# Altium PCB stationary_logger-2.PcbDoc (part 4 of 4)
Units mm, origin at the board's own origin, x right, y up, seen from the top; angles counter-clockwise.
Board outline 105 x 45 mm, 4 copper layers (Top Layer, Layer 2, Layer 3, Bottom Layer), stack 1.492 mm thick; 317 components, 187 nets, 816 pads, 302 vias.
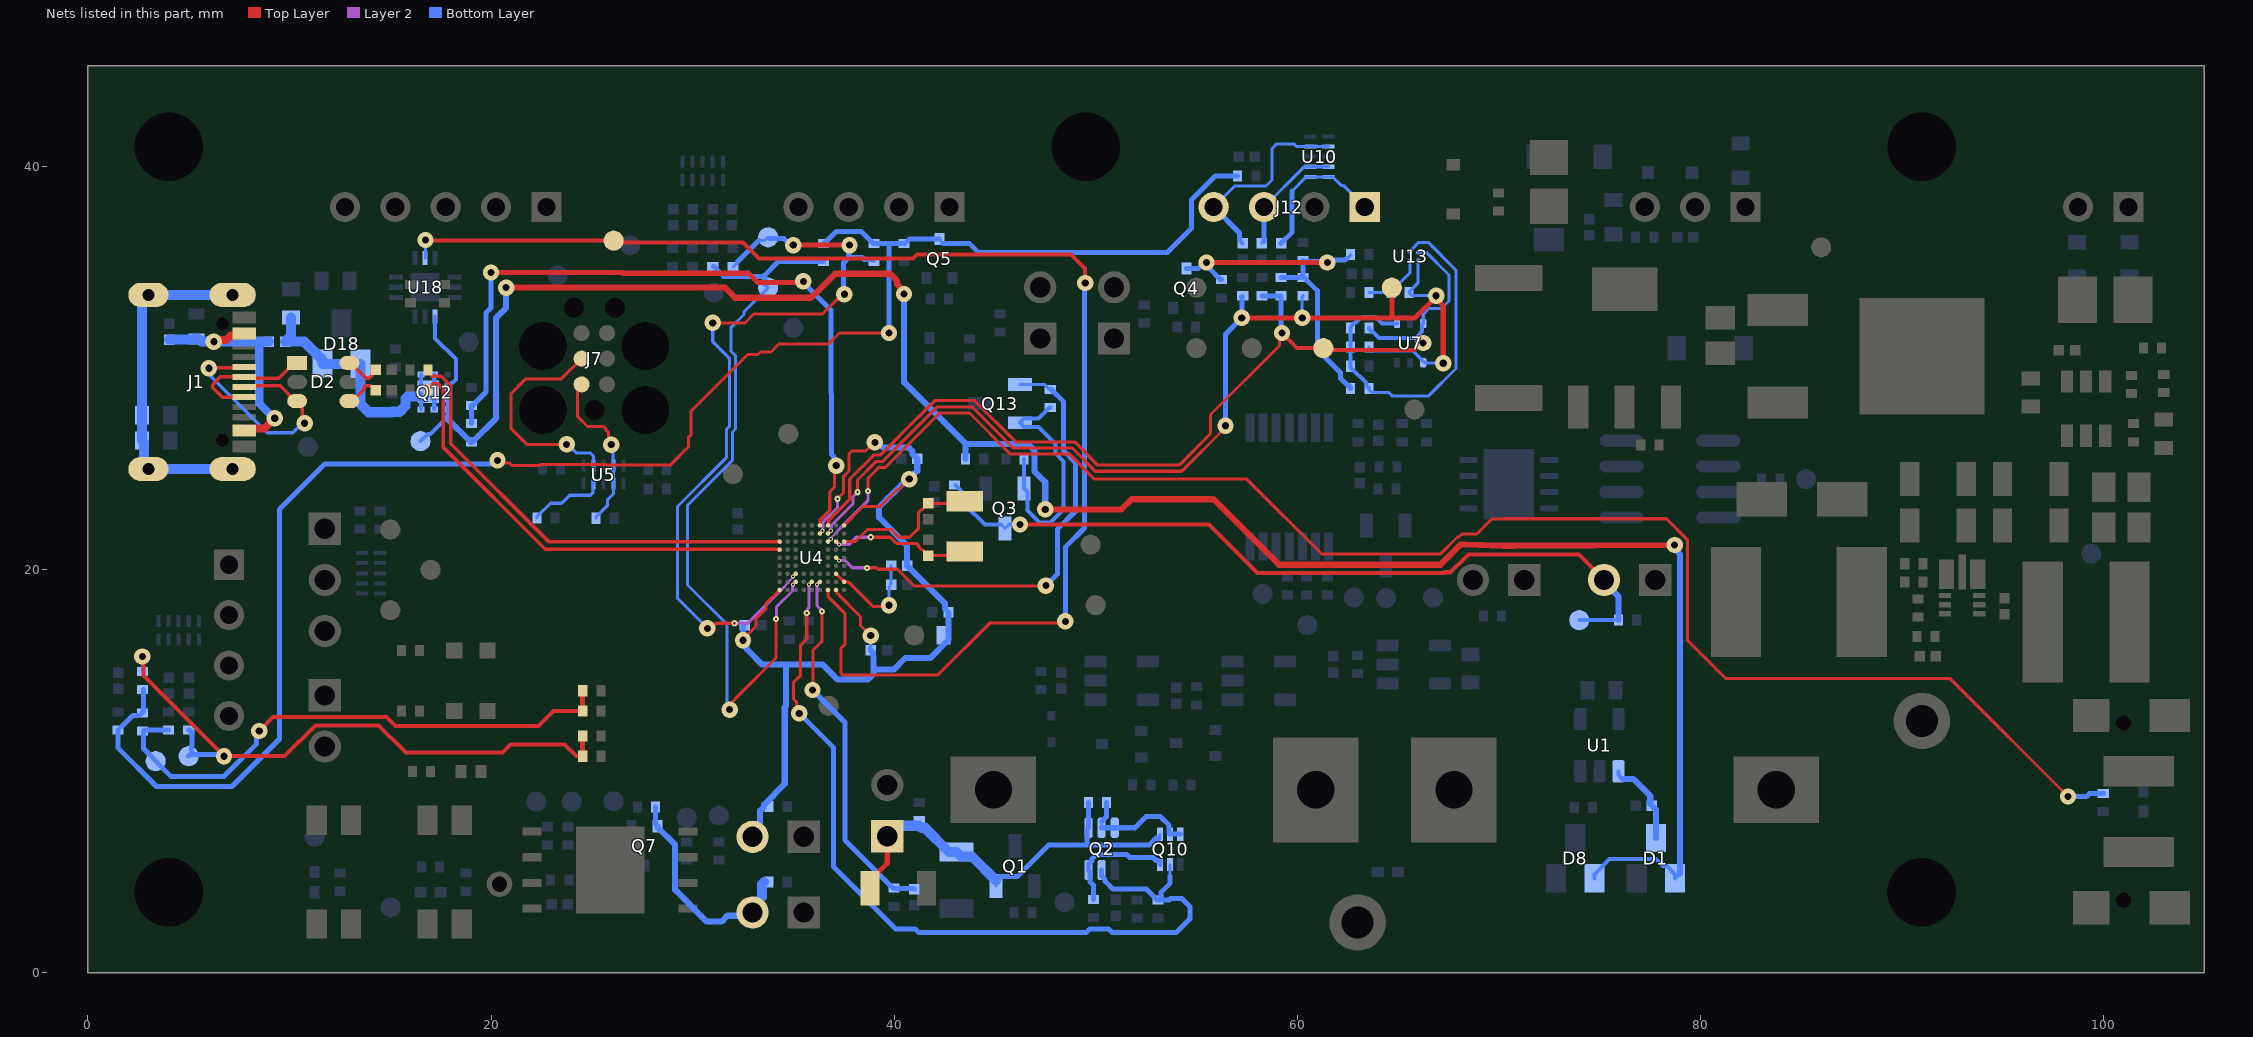
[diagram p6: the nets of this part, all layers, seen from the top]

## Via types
v1: diameter 0.813, hole 0.356, Top Layer to Bottom Layer, tented both sides, 238 vias
v2: diameter 0.305, hole 0.102, Top Layer to Layer 2, tented both sides, 29 vias
v3: diameter 0.203, hole 0.102, Top Layer to Layer 2, tented both sides, 27 vias
v4: diameter 0.305, hole 0.13, Top Layer to Bottom Layer, tented both sides, 8 vias

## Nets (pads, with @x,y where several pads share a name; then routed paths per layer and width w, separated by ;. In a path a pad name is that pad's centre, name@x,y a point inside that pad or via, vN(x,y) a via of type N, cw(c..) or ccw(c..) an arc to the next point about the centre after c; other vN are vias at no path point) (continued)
SENSE.VBAT_MEAS_EN: Q2.2 Q10.2 R17.1 U4.H5 | length 42.4
  Top Layer w0.152: v1(35.292,12.876) 35.166,13.002 35.166,13.433 35.012,13.587 35.012,14.424 35.361,14.773 35.361,16.262 35.666,16.567 v2(35.666,17.851)
  Layer 2 w0.152: 35.695,18.038 35.768,18.111 35.768,19.152 35.774,19.158 35.774,19.254 v3(35.783,19.263)
  Bottom Layer w0.152: 53.7,4.8 Q10.2@53.7,5.38
  Bottom Layer w0.25: v1(35.292,12.876) 37,11.167 37,5.25 40.066,2.184 41.033,2.184 41.217,2 49.533,2 49.717,2.184 50.641,2.184 50.825,2 54,2 54.684,2.684 54.684,3.283 54.283,3.684 53.717,3.684 53.657,3.624 R17.1@53.15,3.624 ; Q2.2@50.3,5.1 50.3,4.8 50.473,4.627 50.473,4.544 50.854,4.162 52.512,4.162 53.05,3.624 R17.1@53.1,3.624 R17.1@53.15,3.624 ; 53.7,4.8 53.7,4.45 53.25,4 53.25,3.724 R17.1@53.15,3.624
SWCLK: J7.4 R39.1 U5.4 U5.7 | length 15.7
  Top Layer w0.152: v1(23.75,26.222) 21.778,26.222 21,27 21,28.75 21.722,29.472 23.491,29.472 J7.4@24.492,30.473
  Bottom Layer w0.152: R39.1@22.275,22.575 22.275,22.625 22.952,23.302 23.502,23.302 23.9,23.7 24.928,23.7 25.053,23.825 25.053,24.248 U5.4@25.077,24.272 U5.7@25.077,25.172 25.077,25.646 24.935,25.787 24.604,25.787 24.589,25.802 24.228,25.802 23.808,26.222 v1(23.75,26.222)
SWDIO: J7.2 R37.1 U5.2 U5.9 | length 8.3
  Top Layer w0.152: J7.2@24.492,29.203 24.492,29.028 24.3,28.836 24.3,27.6 24.79,27.11 25.589,27.11 25.695,27.004 25.695,26.945 25.835,26.805 25.835,26.338 v1(25.962,26.212)
  Bottom Layer w0.152: R37.1@25.202,22.56 25.202,22.61 25.788,23.195 25.788,23.488 26.077,23.777 U5.2@26.077,24.272 U5.9@26.077,25.172 26.053,25.196 26.053,26.12 v1(25.962,26.212)
TEMP_ADD0: R52.1 R53.1 R55.1 R58.1 U7.4 U13.B2 | length 19.1
  Bottom Layer w0.152: R53.1@63.557,29 63.557,28.95 63.705,28.801 64.551,28.801 64.737,28.615 66.51,28.615 67.883,29.988 67.883,34.867 66.5,36.25 66.042,36.25 65.678,35.886 65.678,35.834 65.607,35.763 U13.B2@65.607,35.75
  Bottom Layer w0.2: R53.1@63.557,29 63.432,29.125 63.432,29.275 62.657,30.05 R52.1@62.657,30.1 R58.1@62.657,31.05 62.657,32.051 62.869,32.263 62.93,32.263 63.195,32.528 63.915,32.528 64.218,32.225 U7.4@64.957,32.225
TEMP_ADD1: R4.1 R83.2 U13.A2 | length 3.1
  Bottom Layer w0.152: R4.1@63.557,33.75 R83.2@64.657,33.75 64.657,33.8 65.607,34.75 U13.A2@65.607,35.35
TEMPA_I2C.SCL: R60.2 R91.2 R94.1 R97.2 TP37.1 | length 31.2
  Top Layer w0.2: v1@2.75,16 2.75,14.75 v1(6.75,10.75) 9.75,10.75 11.282,12.282 14.422,12.282 15.772,10.932 20.567,10.932 20.977,11.343 23.657,11.343 24.25,10.75 R97.2@24.55,10.75
  Top Layer w0.25: R97.2@24.55,10.75 R60.2@24.55,11.75
  Bottom Layer w0.152: R91.2@2.7,14.97 v1(2.7,15.699)
  Bottom Layer w0.25: TP37.1@5,10.75 TP37.1@5.084,10.834 ; R94.1@5,12.05 5.05,12.05 5.15,11.95 5.15,11.82 5.166,11.804 5.166,11.271 5.144,11.249 5.144,10.894 TP37.1@5.084,10.834 ; v1(6.75,10.75) 6.666,10.834 TP37.1@5.084,10.834
TEMPA_I2C.SDA: R51.2 R73.2 R92.2 R93.1 TP24.1 | length 27.6
  Top Layer w0.2: v1(8.5,12) 9.193,12.693 14.807,12.693 15.25,12.25 22.361,12.25 23.111,13 R51.2@24.55,13
  Top Layer w0.25: R51.2@24.55,13 R73.2@24.55,14.07
  Bottom Layer w0.152: R92.2@2.702,11.978 R92.2@2.773,12.05 ; v1@8.374,11.874 v1(8.5,12)
  Bottom Layer w0.25: R92.2@2.75,11.93 2.75,11.131 3.358,10.523 TP24.1@3.358,10.502 4.11,9.75 6.75,9.75 8.374,11.374 v1@8.374,11.874 ; R92.2@2.773,12.05 R93.1@4,12.05
TEMPF_I2C.SCL: R23.2 R89.1 TP17.1 U4.H3 | length 37.9
  Top Layer w0.152: v1(31.836,13.062) 31.963,13.188 31.963,13.444 32.268,13.75 34.142,15.624 v2(34.142,17.552)
  Layer 2 w0.152: v2(34.142,17.552) 34.167,17.577 34.167,18.162 34.955,18.949 34.955,19.152 34.974,19.171 34.974,19.254 v3(34.983,19.263)
  Bottom Layer w0.152: R89.1@31,35.05 R89.1@31.05,35.05 ; v1(31.836,13.062) 31.71,13.188 31.71,17.29 29.75,19.25 29.75,23.207 31.98,25.437 31.98,26.836 32.128,26.984 32.128,30.626 31.9,30.855 31.9,32.013 32.553,32.667 32.553,32.803 TP17.1@33.75,34 TP17.1@33.588,34.162 ; 33.551,34.596 33.588,34.559
  Bottom Layer w0.25: R89.1@31.05,35.05 31.541,34.559 31.599,34.559 31.61,34.548 32.39,34.548 32.401,34.559 33.588,34.559 TP17.1@33.588,34.162 ; 33.551,34.596 34.254,35.3 R23.2@36.5,35.3
TEMPF_I2C.SDA: R24.2 R88.1 TP15.1 U4.G3 | length 40.3
  Top Layer w0.152: v1(30.738,17.094) 30.917,17.094 31.171,17.349 v2(32.085,17.349) ; v1(31,32.25) 32.604,32.25 33.044,32.69 36.44,32.69 37.426,33.676 v1(37.535,33.676) ; v3(34.983,19.663) U4.G3@35.12,19.8
  Top Layer w0.25: v1(35,36.113) v1(37.785,36.113)
  Layer 2 w0.102: 34.588,19.19 34.588,19.2 34.818,19.43 34.818,19.471 34.983,19.636 v3(34.983,19.663)
  Layer 2 w0.152: v2(32.085,17.349) 32.746,17.349 34.588,19.19
  Bottom Layer w0.152: v1(30.738,17.094) 29.25,18.583 29.25,23.138 31.675,25.563 31.675,26.963 31.823,27.111 31.823,30.5 31,31.323 v1(31,32.25) ; R88.1@32,35.05 32.05,35.05 32.199,35.199 R88.1@32.199,35.249 ; TP15.1@33.288,36.338 33.588,36.338 TP15.1@33.75,36.5 TP15.1@33.818,36.432 ; R24.2@38.894,35.406 R24.2@39,35.3
  Bottom Layer w0.25: R88.1@32.199,35.249 TP15.1@33.288,36.338 ; TP15.1@33.818,36.432 34.529,36.432 34.848,36.113 v1(35,36.113) ; v1(37.535,33.676) 37.5,33.712 37.5,35.25 37.75,35.5 ; v1(37.785,36.113) 37.75,36.079 37.75,35.5 ; R24.2@38.894,35.406 38.496,35.406 38.403,35.5 37.75,35.5
TEMPV_I2C.SCL: R19.2 R58.2 R62.1 R83.1 TP9.1 U4.B7 U7.1 U13.A3 | length 55.7
  Top Layer w0.152: U4.B7@36.72,21.8 v3(36.857,21.937) ; v2(38.181,23.851) 38.181,24.452 39.111,25.382 39.439,25.382 40.609,26.552 40.609,26.558 42.136,28.085 43.864,28.085 45.906,26.044 47.747,26.044 47.748,26.043 48.835,26.043 49.987,24.89 54.27,24.89 56.443,27.064 v1(56.443,27.147) ; v1(66.898,33.602) 66.923,33.577 v1@66.949,33.551
  Top Layer w0.25: v1(57.25,32.5) v1(60.25,32.5) 64.7,32.5 ; TP9.1@64.7,34 64.7,32.5 ; v1@66.923,33.577 65.847,32.5 64.7,32.5 ; v1@66.949,33.551 66.949,33.399 67.25,33.098 v1(67.25,30.25)
  Layer 2 w0.152: v3(36.857,21.937) 36.866,21.946 36.866,22.08 36.885,22.099 36.885,22.2 37.952,23.267 37.952,23.61 38.181,23.839 v2(38.181,23.851)
  Bottom Layer w0.152: R62.1@57.25,33.547 R62.1@57.3,33.597 ; v1(60.25,32.5) 60.25,33.548 R19.2@60.3,33.597 ; R58.2@63.557,31.05 63.557,31 63.705,30.851 65.755,30.851 66.257,30.35 66.257,30.324 66.318,30.263 67.237,30.263 v1(67.25,30.25) ; U13.A3@66.007,35.35 66.007,34.25 65.557,33.8 R83.1@65.557,33.75 65.704,33.602 v1(66.898,33.602)
  Bottom Layer w0.25: v1(56.443,27.147) 56.443,31.693 v1(57.25,32.5) 57.275,32.525 57.275,33.522 R62.1@57.25,33.547
TEMPV_I2C.SDA: R20.2 R55.2 R61.1 TP8.1 U4.A7 U7.6 U13.B3 | length 49.7
  Top Layer w0.152: U4.A7@36.72,22.2 36.72,22.22 36.758,22.258 36.758,22.454 37.8,23.496 37.8,24.502 38.984,25.687 39.313,25.687 40.304,26.679 40.304,26.684 42.01,28.39 43.99,28.39 46.032,26.348 47.873,26.348 47.874,26.347 48.961,26.347 50.114,25.195 54.143,25.195 55.705,26.757 55.705,27.705 59.124,31.124 59.124,31.624 v1(59.25,31.75)
  Top Layer w0.2: v1(59.25,31.75) 60,31 TP8.1@61.3,31 61.4,30.9 65.829,30.9 66.181,31.252 v1(66.252,31.252)
  Bottom Layer w0.152: U13.B3@66.007,35.75 66.411,35.75 67.533,34.628 67.533,33.339 67.161,32.967 66.545,32.967 66.257,32.679 U7.6@66.257,32.225
  Bottom Layer w0.2: R55.2@63.557,32.001 63.557,31.951 63.682,31.826 63.732,31.826 64.057,31.5 65.883,31.5 ; 65.944,31.561 66.207,31.824 66.207,32.175 U7.6@66.257,32.225
  Bottom Layer w0.25: R61.1@58.25,33.597 R20.2@59.2,33.597 59.2,31.8 v1(59.25,31.75)
USB.D_N: R8.1 U4.D1 | length 22.7
  Top Layer w0.178: R8.1@16.88,28.92 17.016,29.056 17.016,29.125 17.121,29.229 17.372,29.229 17.619,28.982 17.619,26.092 22.692,21.019 32.919,21.019 32.928,21.009 33.159,21.009 34.277,21.009 34.287,21 U4.D1@34.32,21
USB.D_P: R9.1 U4.C1 | length 22.7
  Top Layer w0.178: R9.1@16.88,29.92 17.016,29.784 17.016,29.715 17.121,29.61 17.53,29.61 18,29.14 18,26.25 22.85,21.4 33.076,21.4 33.086,21.39 33.159,21.39 34.311,21.39 U4.C1@34.32,21.4
USB.DETECT: R5.1 R7.2 U4.A6 | length 36.8
  Top Layer w0.152: v1@35.438,34.25 v1(35.5,34.312) ; U4.A6@36.32,22.2 36.334,22.214 36.334,22.487 36.809,22.962 36.809,23.862 37.038,24.091 37.038,25.08 v1(37.126,25.169)
  Top Layer w0.25: v1(20,34.75) 26.505,34.75 26.54,34.715 32.785,34.715 33.25,34.25 v1@35.438,34.25
  Bottom Layer w0.152: 19.724,32.724 19.75,32.75 ; v1@35.5,34.25 v1(35.5,34.312) ; 36.865,28.737 36.885,28.717 ; v1@37,25.295 v1(37.126,25.169)
  Bottom Layer w0.25: R5.1@19.032,27.25 R7.2@19.032,28.15 19.082,28.15 19.75,28.818 19.75,32.75 20,33 v1(20,34.75) ; v1@35.5,34.25 36.865,32.885 36.865,28.737 ; 36.885,28.717 36.885,25.745 36.991,25.639 36.991,25.605 37.019,25.578 37.019,25.314 v1@37,25.295
USB.DISCONN: Q13.1 R22.2 U4.E8 | length 23.4
  Top Layer w0.152: v2@38.673,20.102 39.122,20.102 39.198,20.026 40.165,20.026 40.986,19.205 47.513,19.205 v1@47.524,19.216
  Layer 2 w0.152: v3@37.266,20.463 37.272,20.457 37.571,20.457 37.927,20.102 v2@38.653,20.102 ; v2@38.673,20.102 38.841,20.102
  Bottom Layer w0.152: Q13.1@46.241,29.2 47.45,29.2 47.7,28.95 R22.2@47.75,28.95
  Bottom Layer w0.25: v1(47.534,19.216) 48.098,19.78 48.098,22.013 49,22.915 49,25.318 48.414,25.904 48.414,28.336 47.8,28.95 R22.2@47.75,28.95
  other v2: 38.663,20.092
  other v3: 37.257,20.463
USB.nFLT: TP14.1 U4.J7 U18.11 | length 69.2
  Top Layer w0.152: U4.J7@36.72,19 36.726,18.994 36.726,18.659 37.574,17.811 37.574,17.428 37.571,17.425 37.571,16.316 37.365,16.11 37.365,14.859 37.454,14.77 42.154,14.77 44.739,17.355 48.415,17.355 v1(48.5,17.44)
  Top Layer w0.2: v1(16.75,36.367) 16.768,36.349 25.986,36.349 26.084,36.251 32.499,36.251 33.293,35.457 40.933,35.457 41.132,35.656 48.772,35.656 49.484,34.944 v1(49.484,34.234)
  Bottom Layer w0.152: U18.11@16.73,35.47 16.74,35.48 16.74,36.358 v1(16.75,36.367)
  Bottom Layer w0.25: v1(48.5,17.44) 48.5,21.123 49.449,22.071 49.449,33.914 49.484,33.949 v1(49.484,34.234)
USB_CONN_D_N: D2.3 J1.A7 J1.B7 | length 12.4
  Top Layer w0.178: v1(6,30) 6.035,30.035 7.72,30.035 J1.B7@7.755,30.07 ; J1.A7@7.755,29.07 7.814,29.129 8.92,29.129 9.54,29.13 10.299,28.37 10.391,28.37 10.628,28.133 10.628,27.397 v1(10.749,27.276)
  Bottom Layer w0.178: v1(6,30) 6.122,29.879 6.122,29.578 8.9,26.8 10.169,26.8 10.645,27.276 v1(10.749,27.276)
USB_CONN_D_P: D2.1 J1.A6 J1.B6 | length 6.6
  Top Layer w0.178: J1.B6@7.755,28.57 6.656,28.57 6.187,29.039 6.187,29.187 6.57,29.57 J1.A6@7.755,29.57 7.814,29.51 8.762,29.51 9.471,29.511 10.23,30.27 D2.1@10.38,30.27
USB_CONN_VBUS: C7.2 D19.K FB1.1 J1.A4_B9 J1.B4_A9 | length 12.6
  Top Layer w0.4: v1(6.25,31.32) 6.329,31.399 6.861,31.399 7.082,31.62 7.655,31.62 J1.A4_B9@7.755,31.72 ; J1.B4_A9@7.755,26.92 7.855,27.02 8.77,27.02 v1(9.268,27.518)
  Bottom Layer w0.4: 8.5,31.32 8.5,28.25 9.232,27.518 v1(9.268,27.518)
  Bottom Layer w0.5: C7.2@4.03,31.42 5.225,31.42 5.255,31.45 D19.K@5.38,31.45 5.505,31.45 5.635,31.32 v1(6.25,31.32) 8.5,31.32 FB1.1@8.98,31.32
USB_ESD_D_N: D2.4 FB9.1 | length 1.8
  Top Layer w0.178: D2.4@12.97,28.37 13.12,28.37 13.707,28.956 13.707,29.082 13.754,29.129 14.005,29.129 14.043,29.091 14.109,29.091 FB9.1@14.28,28.92
USB_ESD_D_P: D2.6 FB10.1 | length 1.8
  Top Layer w0.178: D2.6@12.97,30.27 13.035,30.27 13.795,29.51 13.958,29.51 14.109,29.662 14.109,29.749 FB10.1@14.28,29.92
USB_SHIELD: C11.1 J1.S1 J1.S2 J1.S3 J1.S4 R6.1 | length 17.3
  Bottom Layer w0.5: J1.S4@7.18,25 J1.S3@3,25 2.78,25.22 2.78,26.32 C11.1@2.68,26.42 R6.1@2.68,27.67 2.68,33.409 2.911,33.64 J1.S2@3,33.64 J1.S1@7.18,33.64
USER_BUTTON: R33.1 U4.C7 | length 78.9
  Top Layer w0.152: U4.C7@36.72,21.4 v3(36.857,21.537) ; v2(38.714,23.902) 38.714,24.554 39.237,25.077 39.565,25.077 40.914,26.426 40.914,26.432 42.262,27.781 43.738,27.781 45.779,25.739 47.621,25.739 47.622,25.738 48.709,25.738 49.947,24.5 57.5,24.5 61.207,20.793 67.118,20.793 67.954,21.629 68.025,21.629 68.176,21.78 68.912,21.78 69.656,22.524 70.229,22.524 70.238,22.533 78.325,22.533 79.365,21.493 79.365,16.515 81.28,14.6 92.4,14.6 v1(98.25,8.75)
  Layer 2 w0.102: v3(36.857,21.537) 36.857,21.564 37.022,21.729 37.022,21.761 37.195,21.934 37.204,21.934
  Layer 2 w0.152: 37.204,21.934 38.714,23.444 v2(38.714,23.902)
  Bottom Layer w0.25: v1(98.25,8.75) 99.178,8.75 99.328,8.9 R33.1@100,8.9
VAX_SCL: FB5.2 J12.4 U10.4 U10.7 | length 10.4
  Bottom Layer w0.152: J12.4@55.857,38 56.903,39.046 58.457,39.046 58.75,39.339 58.75,40.893 58.992,41.135 59.824,41.135 59.959,41 U10.4@60.657,41 U10.7@61.557,41
  Bottom Layer w0.2: FB5.2@57.14,36.357 FB5.2@57.3,36.197
  Bottom Layer w0.25: J12.4@55.857,38 57.14,36.717 FB5.2@57.14,36.357
VAX_SDA: FB4.2 J12.3 U10.2 U10.9 | length 5.9
  Bottom Layer w0.152: FB4.2@58.25,36.197 FB4.2@58.357,36.304 ; J12.3@58.357,38 60.357,40 U10.2@60.657,40 U10.9@61.557,40
  Bottom Layer w0.25: FB4.2@58.357,36.304 J12.3@58.357,38
VAX_VDD: FB3.2 J12.1 U10.1 U10.10 | length 7.3
  Bottom Layer w0.152: 59.75,38.793 60.457,39.5 U10.1@60.657,39.5 U10.10@61.557,39.5 61.757,39.5 62.182,39.075 62.282,39.075 J12.1@63.357,38
  Bottom Layer w0.25: FB3.2@59.2,36.197 59.75,36.747 59.75,38.793
VB1: Q2.5 Q2.6 Q10.5 Q10.6 R15.2 | length 6.1
  Bottom Layer w0.152: Q2.5@50.3,7.2 Q2.5@50.3,7.513
  Bottom Layer w0.25: Q2.5@50.3,7.2 Q2.6@50.95,7.2 51.95,7.2 52.5,7.75 53.222,7.75 53.652,7.32 53.652,6.927 Q10.5@53.7,6.88 Q10.6@54.2,6.88 ; Q2.5@50.3,7.513 50.55,7.763 R15.2@50.55,8.45
VB2: Q2.3 Q10.3 R16.1 | length 5.9
  Bottom Layer w0.25: R16.1@49.9,3.65 49.9,4.35 49.725,4.525 49.725,5.025 Q2.3@49.65,5.1 49.65,5.4 49.823,5.573 49.823,5.656 50.049,5.882 51.531,5.882 51.683,5.731 52.849,5.731 53,5.58 53.15,5.58 53.2,5.53 Q10.3@53.2,5.38
VBAT: C12.2 C23.2 J2.1 Q1.2 Q2.4 Q10.4 R12.1 R15.1 | length 21.4
  Top Layer w0.254: C23.2@38.8,4.2 38.8,4.575 39.662,5.437 J2.1@39.662,6.78
  Bottom Layer w0.152: Q1.2@45.05,4.309 Q1.2@45.05,4.592 ; 50.202,6.334 50.251,6.285 ; Q10.4@53.15,6.68 53.2,6.73 Q10.4@53.2,6.88
  Bottom Layer w0.25: Q1.2@45.05,4.592 45.243,4.784 46.115,4.784 47.664,6.334 49.5,6.334 ; R15.1@49.65,8.45 Q2.4@49.65,7.2 49.575,7.125 49.575,6.409 49.5,6.334 ; Q10.4@53.15,6.68 53,6.68 52.654,6.334 50.202,6.334 49.5,6.334
  Bottom Layer w0.5: J2.1@39.662,6.78 40.181,7.3 41.25,7.3 41.35,7.2 41.525,7.2 42.725,6 C12.2@43.1,6 43.325,5.775 43.867,5.775 Q1.2@45.05,4.592
VBAT_MEAS_FILT: C3.2 R117.1 U4.H6 | length 18.3
  Top Layer w0.152: v1(35.952,14.034) 35.977,14.06 35.977,16.016 36.428,16.467 v2(36.428,17.933) ; v3(36.183,19.263) U4.H6@36.32,19.4
  Layer 2 w0.152: v3(36.183,19.263) 36.174,19.254 36.174,18.218 36.428,17.964 v2(36.428,17.933)
  Bottom Layer w0.25: v1(35.952,14.034) 37.566,12.42 37.566,6.584 39.95,4.2 R117.1@40,4.2 40.025,4.175 40.975,4.175 C3.2@41,4.15
VBUS: D1.1 D8.1 Q12.S R5.2 R25.1 TP1.1 U18.4 | length 109.8
  Top Layer w0.3: v1(20.75,34) 31.612,34 32.112,33.5 35.887,33.5 37.077,34.69 39.8,34.69 40.15,34.34 40.15,34.163 40.491,33.822 v1(40.491,33.683) ; v1(47.5,23) 51.286,23 51.786,23.5 55.861,23.5 59.111,20.25 67.111,20.25 68.023,21.162 68.111,21.25 68.36,21.25 70.207,21.194 70.793,21.194 v1(78.73,21.23)
  Bottom Layer w0.2: TP1.1@16.5,26.382 16.868,26.75 17,26.75 17.832,27.582 Q12.S@17.832,27.945 17.832,29.07 18.057,29.295 18.111,29.295 18.257,29.441 18.257,30.451 17.23,31.477 17.23,32.345 U18.4@17.23,32.57 ; D8.1@74.75,4.691 74.75,4.891 75.502,5.643 77.798,5.643 78.15,5.291 78.35,5.291 78.75,4.891 D1.1@78.75,4.691 D1.1@79,4.941 ; v1(78.73,21.23) 78.73,21.064 78.924,20.87 ; 78.924,20.826 79,20.75
  Bottom Layer w0.3: 17.832,27.582 17.832,27.5 18.982,26.35 R5.2@19.032,26.35 19.082,26.35 20.25,27.518 20.25,32.5 20.75,33 v1(20.75,34) ; v1(40.491,33.683) 40.5,33.674 40.5,29.3 43.55,26.25 ; R25.1@43.55,25.5 43.55,26.25 ; v1(47.5,23) 47.5,24.35 46.977,24.873 46.977,25.9 46.628,26.25 43.55,26.25 ; 78.924,20.826 78.924,20.87 ; D1.1@79,4.941 79,20.75
VBUS_FILT: C8.2 D18.1 D18.2 FB1.2 Q12.D R95.2 | length 15.5
  Bottom Layer w0.2: Q12.D@16.532,27.945 16.532,28.47 16.661,28.599 Q12.D@16.882,28.82 ; Q12.D@16.532,29.695 16.532,29.17 Q12.D@16.882,28.82 ; Q12.D@17.182,27.945 17.182,28.52 Q12.D@16.882,28.82 ; Q12.D@17.182,29.695 17.182,29.12 Q12.D@16.882,28.82
  Bottom Layer w0.5: C8.2@10.08,32.52 10.08,31.62 FB1.2@9.78,31.32 10.73,31.32 11.63,30.42 D18.2@11.63,30.22 D18.1@13.53,30.22 13.53,28.22 13.933,27.817 R95.2@15.08,27.817 15.105,27.842 15.465,27.842 15.758,28.135 15.758,28.5 15.857,28.599 Q12.D@16.661,28.599
VDD_FLASH: J15.2 Q7.S R71.2 R72.1 | length 10.9
  Bottom Layer w0.152: Q7.S@28.16,7.375 Q7.S@28.26,7.275
  Bottom Layer w0.25: Q7.S@28.16,7.375 R72.1@28.16,8.225
  Bottom Layer w0.3: Q7.S@28.26,7.275 28.26,7.225 29.133,6.352 29.133,4.115 30.706,2.541 31.438,2.541 31.73,2.833 32.813,2.833 J15.2@32.98,3
  Bottom Layer w0.5: J15.2@32.98,3 32.98,3.298 33.45,3.768 33.45,4.4 33.55,4.5
VDD_MCU: C18.2 C19.2 C20.2 C21.2 C22.2 FB2.1 J6.2 R21.2 U4.A9 U4.B6 U4.J1 U4.J8 | length 54
  Top Layer w0.152: v1(32.5,16.5) 32.5,16.546 33.139,17.186 33.139,17.565 33.653,18.079 33.653,18.333 U4.J1@34.32,19 ; U4.J8@37.12,19 37.134,18.986 37.134,18.878 38.336,17.676 38.336,17.234 38.835,16.735 v1(38.842,16.735) ; v2(37.19,23.526) 37.495,23.831 37.495,24.639 37.761,24.906 37.761,25.761 37.89,25.89 38.583,25.89 39.015,26.322 v1(39.05,26.322) ; U4.A9@37.52,22.2 38.46,23.14 39.316,23.14 40.139,23.963 40.213,23.963 v1(40.75,24.5)
  Layer 2 w0.152: v3(36.457,21.937) 36.466,21.946 36.466,22.061 36.479,22.073 36.479,22.378 37.19,23.089 v2(37.19,23.526)
  Bottom Layer w0.152: C19.2@32.5,17.15 C19.2@32.6,17.25 ; 33.55,8.25 33.55,8.35 ; v1(38.842,16.735) 38.842,16.184 38.758,16.1 38.75,16.1 C22.2@38.85,16 ; v1@40.654,24.5 v1(40.75,24.5) ; C20.2@42.516,18.074 C20.2@42.7,17.89
  Bottom Layer w0.25: v1(32.5,16.5) C19.2@32.5,17.15
  Bottom Layer w0.3: v1(32.5,16.5) 32.5,16.361 32.681,16.181 32.681,16.069 33.454,15.296 34.635,15.296 ; J6.2@32.98,6.75 32.98,7.102 33.35,7.472 33.35,8.05 33.55,8.25 ; 33.55,8.35 34.574,9.374 34.574,13.176 34.635,13.237 34.635,15.296 ; C22.2@38.85,16 38.96,15.89 38.96,15.742 38.987,15.714 38.987,15.046 ; v1(39.05,26.322) 39.188,26.322 39.448,26.062 40.735,26.062 40.912,25.885 40.912,25.738 C21.2@41.15,25.5 41.15,24.913 40.75,24.513 v1(40.75,24.5) ; v1@40.654,24.5 39.958,23.804 39.946,23.804 39.593,23.451 39.593,23.439 39.25,23.096 39.25,22.602 40.65,21.202 FB2.1@40.65,20.2 42.516,18.334 C20.2@42.516,18.074 ; C20.2@42.7,17.89 42.7,16.52 41.81,15.63 40.567,15.63 39.984,15.046 38.987,15.046 ; 34.635,15.296 36.454,15.296 37.204,14.546 38.704,14.546 38.987,14.83 38.987,15.046
VDD_TEMPF: Q5.D R23.1 R24.1 R57.1 R87.1 R90.1 R91.1 R92.1 | length 88.1
  Top Layer w0.152: v1(20.319,25.431) 20.445,25.305 20.902,25.305 21.028,25.18 22.4,25.18 22.447,25.226 25.678,25.226 25.709,25.195 28.889,25.195 29.791,26.097 29.791,26.564 29.931,26.704 29.931,27.876 32.737,30.682 33.251,30.682 33.378,30.81 33.892,30.81 34.292,31.21 36.753,31.21 37.293,31.75 v1(39.75,31.75)
  Bottom Layer w0.152: R90.1@1.5,12.05 R90.1@1.649,12.199 ; R92.1@2.702,12.918 R92.1@2.75,12.966 ; R57.1@40.5,36.2 R57.1@40.55,36.2 ; Q5.D@42.25,36.422 42.25,36.372 Q5.D@42.424,36.198
  Bottom Layer w0.25: R90.1@1.5,12.05 1.5,11.15 3.4,9.25 7.148,9.25 8.267,10.368 9.5,11.602 9.5,23 11.75,25.25 19.985,25.25 20.166,25.431 v1(20.319,25.431) ; R90.1@1.649,12.199 2.23,12.78 2.563,12.78 R92.1@2.702,12.918 ; R92.1@2.75,12.966 R91.1@2.75,14.05 ; R23.1@36.5,36.2 36.55,36.2 37.147,36.797 38.353,36.797 38.95,36.2 R24.1@39,36.2 39.75,36.2 ; v1(39.75,31.75) 39.75,36.2 ; R57.1@40.5,36.2 39.75,36.2 ; R57.1@40.55,36.2 40.772,36.422 Q5.D@42.25,36.422 ; Q5.D@42.424,36.198 43.733,36.198 44.181,35.75 53.569,35.75 54.75,36.931 54.75,38.346 55.953,39.55 R87.1@57.05,39.55
VDD_TEMPV: Q4.D R19.1 R20.1 R48.1 R50.1 R53.2 R59.1 | length 19.4
  Top Layer w0.25: v1(55.5,35.25) v1(61.5,35.25)
  Bottom Layer w0.152: R19.1@60.3,34.497 R19.1@60.35,34.497 ; R59.1@60.3,35.347 R59.1@60.348,35.299 ; v1@61.451,35.299 v1(61.5,35.25) v1@61.626,35.376 ; R50.1@62.458,35.452 62.508,35.452 62.657,35.601 R50.1@62.657,35.651
  Bottom Layer w0.25: Q4.D@54.5,34.947 55.094,34.947 55.397,35.25 v1(55.5,35.25) 55.608,35.142 55.608,34.989 56.2,34.397 R48.1@56.25,34.397 ; R20.1@59.2,34.497 R19.1@60.3,34.497 R59.1@60.3,35.347 ; R59.1@60.348,35.299 v1@61.451,35.299 ; R19.1@60.35,34.497 61,33.847 61,30.933 62.154,29.779 62.154,29.502 62.507,29.15 62.557,29.15 62.657,29.05 R53.2@62.657,29 ; v1@61.626,35.376 62.382,35.376 R50.1@62.458,35.452
VDDA: C17.1 FB2.2 U4.G8 U4.H9 | length 5.3
  Top Layer w0.152: U4.G8@37.12,19.8 U4.H9@37.52,19.4 37.73,19.4 38.943,18.187 39.687,18.187 v1(39.745,18.245)
  Bottom Layer w0.152: v1(39.745,18.245) 39.745,19.145 C17.1@39.85,19.25 FB2.2@39.85,20.2
VDDUSB: Q3.2 Q13.2 R22.1 R28.2 | length 12.4
  Bottom Layer w0.2: R28.2@46.45,25.5 Q3.2@46.45,24.033 46.619,23.865 46.619,22.932 47.207,22.344 47.772,22.344 48.409,22.981 48.409,25.376 48,25.784 48,26.25 47.167,27.083 46.458,27.083 Q13.2@46.241,27.3 46.458,27.518 47.168,27.518 47.7,28.05 R22.1@47.75,28.05
VIN: C9.2 D1.3 U1.1 | length 4.4
  Bottom Layer w0.2: U1.1@75.95,10 75.95,9.825 U1.1@76.15,9.625
  Bottom Layer w0.3: U1.1@76.15,9.625 76.675,9.625 77.522,8.778 77.522,8.378 77.8,8.1 D1.3@77.8,6.691
VSYS: J16.2 Q3.3 R1.2 R29.2 TP3.1 | length 39.6
  Top Layer w0.2: v1(46.25,22.25) 55.625,22.25 58.027,19.848 67.278,19.848 67.309,19.879 67.62,19.879 68.294,20.552 68.302,20.552 68.5,20.75 73.98,20.75 J16.2@75.23,19.5
  Bottom Layer w0.152: R29.2@43,24.2 R29.2@43.05,24.2 ; Q3.3@45.302,22.25 Q3.3@45.5,22.052 Q3.3@45.698,22.25
  Bottom Layer w0.2: R29.2@43.05,24.2 43.527,23.723 43.527,23.223 44.5,22.25 Q3.3@45.302,22.25 ; Q3.3@45.698,22.25 v1(46.25,22.25) ; TP3.1@74,17.5 75.7,17.5 ; J16.2@75.23,19.121 75.23,19.384 J16.2@75.23,19.5
  Bottom Layer w0.3: J16.2@75.23,19.384 75.95,18.664 R1.2@75.95,17.5
X32_IN: C26.2 U4.C9 Y1.1 | length 7.6
  Top Layer w0.152: U4.C9@37.52,21.4 38.086,21.4 38.46,21.774 38.683,21.997 39.855,21.997 40.237,21.615 40.763,21.615 41.217,22.069 41.217,22.855 41.351,22.989 41.394,22.989 C26.2@41.705,23.3 43.4,23.3 Y1.1@43.5,23.4
X32_OUT: C27.2 U4.C8 Y1.2 | length 7.1
  Top Layer w0.152: U4.C8@37.12,21.4 v3(37.257,21.263) ; v2(38.841,21.616) 39.805,21.616 40.111,21.31 41.095,21.31 41.217,21.189 41.217,21.145 41.351,21.011 41.394,21.011 41.522,20.884 C27.2@41.705,20.7 43.3,20.7 Y1.2@43.5,20.9
  Layer 2 w0.152: v3(37.257,21.263) 37.26,21.26 37.774,21.26 38.13,21.616 v2(38.841,21.616)
pads on no net: D2.5 J1. J1.A8 J1.B8 J7.0 J18.3 MTG1.1 MTG2.1 MTG3.1 MTG4.1 MTG5.1 S1.2 S1.3 S2.2 S2.3 S3.GUIDE U1.4 U2.4 U3.4 U4.C4 U4.C5 U4.F3 U4.F7 U7.3 U11.5 U11.6 U11.9 U11.10 U14.2 U14.4 U14.7 U14.9 U16.4 U17.5 U17.6 U19.5

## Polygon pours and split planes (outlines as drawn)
GND on Top Layer "PGND_TOP" (solid, remove dead copper, pour order 8): 9.15,0.677 86.15,0.677 86.15,8.927 96,8.927 96,0.5 104.5,0.5 104.5,40.927 96.47,40.927 96.47,35.927 86.15,35.927 86.15,40.927 9.15,40.927 9.15,35.927 0.9,35.927 0.9,8.927 9.15,8.927
NetC30_2 on Top Layer "NETC30_2_L01_P006" (solid, pour order 6): 92,26 92,20.8 96,20.8 96,26
GND on Layer 2 "PGND_L2" (solid, remove dead copper, pour order 4): 9,0 86,0 86,9 96,9 96,0 104.5,0 104.5,44.5 96,44.5 96,36 86,36 86,45 9,45 9,36 0,36 0,9 9,9
GND on Layer 3 "PGND_L3" (solid, remove dead copper, pour order 5): 9.5,0 86.5,0 86.5,9 96,9 96,0 104.5,0 104.5,45 96,45 96,36 86.5,36 86.5,45 9.5,45 9.5,36 0.5,36 0.5,9 9.5,9
GND on Bottom Layer "PGND_BOT" (solid, remove dead copper, pour order 7): 9,0.75 86,0.75 86,9 96,9 96,0.5 104.5,0.5 104.5,36 86,36 86,41 9,41 9,36 0.75,36 0.75,9 9,9

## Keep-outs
Keep-Out Layer:
  lines w0.2: 0.2,0.2 0.2,44.8 104.8,44.8 104.8,0.2 0.2,0.2
  text "'.Layer_Name'" at 5,-5 h3

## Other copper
Top Layer:
  text "'.Layer_Name'" at 5,-5 h3
Layer 2:
  text "'.Layer_Name'" at 5,-5 h3
Layer 3:
  text "'.Layer_Name'" at 5,-5 h3
Bottom Layer:
  text "'.Layer_Name'" at 5,-5 h3

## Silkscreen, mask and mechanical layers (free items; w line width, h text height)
Top Overlay:
  region: 43.5,34.8 34,34.8 34,27.8 43.5,27.8
  lines w0.15: 61.25,13.1 60.75,13.1 60.75,14.5 61.25,14.5 ; 61.25,12.3 67.75,12.3 67.75,15.3 61.25,15.3 61.25,12.3
  lines w0.2: 13.4,19.2 14.9,19.2 ; 13.8,20.5 13.4,20.9 ; 13.8,21.3 13.4,20.9 ; 14.5,18.8 14.9,19.2 ; 14.5,19.6 14.9,19.2 ; 14.9,20.9 13.4,20.9 ; 18,9.15 18.25,9.15 ; 18.25,8.9 18.25,9.4 ; 18.75,9.15 19,9.15 ; 66.25,38.5 66.75,38.5 ; 66.5,38.25 66.5,38.5 ; 66.5,39 66.5,39.25 ; 85.5,26 85.75,26 ; 86.25,25.75 86.25,26.25 ; 86.5,26 86.25,26 ; 18.25,9.15 18.75,9.4 18.75,8.9 18.25,9.15 ; 66.5,38.5 66.25,39 66.75,39 66.5,38.5 ; 86.25,26 85.75,26.25 85.75,25.75 86.25,26
  lines w0.254: 91.775,15.125 94.5,12.4 94.5,10.1 96.7,10.1 97.9,8.9 ; 95.3,17.175 95.3,13.8 96,13.1 ; 103,28.25 104,28.25 104,31.75 103.5,31.75 103.5,32.5 ; 103,32.5 104,32.5
  text "LIN" at 85.1,43.9 h1.27 r270
  text "M2MPWR" at 94.25,43.75 h1.27 r270
  text "DOORS" at 25.4,43.5 h1.27 r270
  text "VAX" at 51.5,43.3 h1.27 r270
  text "FRZ" at 45.5,43.2 h1.27 r270
  text "NC" at 16.9,37 h1.27 r270
  text "GND" at 11.9,36.8 h1.27 r270
  text "FRZ" at 13.9,36.8 h1.27 r270
  text "GND" at 18.9,36.8 h1.27 r270
  text "VAX" at 20.5,36.8 h1.27 r270
  text "-" at 39.2,35.6 h1.27
  text "-" at 59.7,35.6 h1.27
  text "-" at 76,35.6 h1.27
  text "+" at 80.2,35.6 h1.27
  text "+" at 40.7,35.4 h1.27
  text "+" at 61.3,35.4 h1.27
  text "LIN" at 77.7,35.4 h1.27
  text "C" at 34.5,35.3 h1.27
  text "D" at 37.2,35.3 h1.27
  text "C" at 55.1,35.3 h1.27
  text "D" at 57.9,35.3 h1.27
  text "PG10" at 56,33.25 h1.27
  text "SN:" at 30.5,33.2 h1.27
  text "SCLV" at 63.9,33.2 h1.27 r270
  text "PG14" at 54,30.3 h1.27 r270
  text "PG13" at 56.8,30.3 h1.27 r270
  text "SDAV" at 60.4,30.2 h1.27 r270
  text "Rev. '.nhProjRev'" at 44.2,27.6 h1.5
  text "PC12" at 29.4,25.9 h1.27
  text ".nhToday" at 44.8,25.7 h1.27
  text "PC11" at 33.2,23.8 h1.27
  text "PG09" at 49,22 h1.27
  text "PC09" at 15.75,21.25 h1.27
  text "NH/GHL Demo EMS Logger" at 54.3,19.5 h1.5
  text "PC08" at 17.9,19.4 h1.27
  text "+" at 8.3,18.2 h1.27
  text "PC07" at 17.9,17.7 h1.27
  text "PD02" at 44.75,17.5 h1.27
  text "-" at 8.3,16.9 h1.27
  text "-" at 13.27,16.288 h1.27
  text "3.0V CR123A" at 58.5,15.5 h1.27
  text "D" at 8.5,14.5 h1.27
  text "PC03" at 39,14.5 h1.27
  text "+" at 63.15,13.15 h1.5 r90
  text "-" at 67.45,13.15 h1.5 r90
  text "C" at 8.4,12 h1.27
  text "GND" at 85.6,11.7 h1.27
  text "PC05" at 34.5,11 h1.27
  text "AMB" at 0.9,8.3 h1.27
  text "RST" at 8.5,7.5 h1.27 r270
  text "BOOT0" at 14.2,7.5 h1.1 r270
  text "BAT+" at 59.25,4.25 h1.27
  text "Licensed under" at 47.75,1.5 h1.27
  text "CERN-OHL-P v2" at 65.5,1.25 h1.27
  text "'.Layer_Name'" at 5,-5 h3
Bottom Overlay:
  circle w0.4: c66,4 r0.2
  lines w0.2: 5,30 5.5,30 ; 5.25,29.75 5.25,30 ; 5.25,30.5 5.25,30.75 ; 5.55,14.95 6.3,14.2 8.4,14.2 9.9,15.7 12.5,15.7 ; 5.6,11.7 5.7,11.8 5.7,11.9 5.7,13.1 6.4,13.8 8.4,13.8 9.9,12.3 9.9,11 11.2,9.7 12.5,9.7 ; 9.75,6.5 10.25,6.5 ; 10,5.75 10,6 ; 10,6.75 10,6.5 ; 13.75,25.25 14,25.5 14,29 14.75,29.75 ; 16.5,3.15 16.75,3.15 ; 16.75,2.9 16.75,3.4 ; 17.25,3.15 17.5,3.15 ; 18.7,29.8 20,31.1 20,31.8 ; 21.25,39.75 21.25,39.45 21.45,39.25 28.35,39.25 28.6,39.5 28.6,39.65 28.6,39.8 ; 27.25,39.25 27.25,38.25 28,37.5 28.5,37.5 ; 32.25,39.75 32.5,39.5 38.25,39.5 38.5,39.75 ; 32.5,36.25 32.75,36.5 32.75,39.5 ; 34,35.75 34,35.5 35.9,33.6 ; 37.1,36.2 37.15,36.25 37.5,36.25 39.2,37.95 39.2,39.45 39.375,39.625 ; 39,30.5 39.5,30.5 ; 39.25,30.25 39.25,30.5 ; 39.25,31 39.25,31.25 ; 39.9,26.8 40.6,26.1 42.65,26.1 43.05,25.7 ; 43.5,36.75 45,38.25 45,40.5 ; 44.75,11 45.25,11 ; 45,10.75 45,11 ; 45,11.5 45,11.75 ; 46.1,36.9 55,36.9 55.25,37.15 ; 53.25,9.05 54.55,7.75 55.3,7.75 ; 54.5,36.9 54.5,36.6 55.35,35.75 56.75,35.75 ; 56.4,11.3 57.1,10.6 57.4,10.6 ; 56.7,19.8 58.9,19.8 ; 58.9,31.3 62.1,31.3 ; 60.75,34 61.25,34.5 61.25,35.75 62,36.5 62,38.5 63,39.5 63,40.25 ; 62.25,40.5 62.5,40.25 69.5,40.25 69.925,40.675 ; 67.4,34 74.2,34 74.6,33.6 74.6,27.3 74.05,26.75 67.5,26.75 67.5,24.75 66,23.25 62.75,23.25 62.5,23.5 62.5,27.75 62.75,28 67.2,28 67.2,32.5 67.2,33.7 67.5,34 67.6,34 ; 72.5,43.575 72.75,43.575 ; 72.75,43.325 72.75,43.825 ; 73.25,43.575 73.5,43.575 ; 78,42.6 78.25,42.6 ; 78.25,42.35 78.25,42.85 ; 78.75,42.6 79,42.6 ; 80.25,29.5 80.5,29.5 ; 80.5,29.25 80.5,29.75 ; 81,29.5 81.25,29.5 ; 5.25,30 5.5,30.5 5,30.5 5.25,30 ; 10,6.5 9.75,6 10.25,6 10,6.5 ; 16.75,3.15 17.25,2.9 17.25,3.4 16.75,3.15 ; 39.25,30.5 39.5,31 39,31 39.25,30.5 ; 45,11 45.25,11.5 44.75,11.5 45,11 ; 72.75,43.575 73.25,43.325 73.25,43.825 72.75,43.575 ; 78.25,42.6 78.75,42.35 78.75,42.85 78.25,42.6 ; 80.5,29.5 81,29.25 81,29.75 80.5,29.5
  lines w0.254: 44.375,7.125 45,6.5
  text "DOORF" at 26,35.3 h1.27
  text "SDAF" at 37.75,34.75 h1.27 r90
  text "SCLF" at 34.25,33.25 h1.27 r90
  text "DOORV" at 31.75,33 h1.27 r90
  text "Licensed under" at 90.25,33 h1.27 r90
  text "CERN-OHL-P v2" at 92.25,33 h1.27 r90
  text "Source package at" at 94.25,33 h1.27 r90
  text "https://docs.2to8.cc" at 96.25,33 h1.27 r90
  text "PC10" at 36,31.25 h1.27 r90
  text "VBUS" at 18.6,27.1 h1.27 r90
  text "GND" at 11.25,27 h1.27
  text "VSYS" at 74.4,22.6 h1.1 r90
  text "PWRnEN" at 26.6,16.2 h1.27 r90
  text "CIPO" at 24.75,13.75 h1.27 r90
  text "COPI" at 30.5,13 h1.27 r90
  text "nCS" at 23,12.75 h1.27 r90
  text "SCK" at 32.25,12.75 h1.27 r90
  text "SCLA" at 7.25,11.5 h1.27 r90
  text "SDAA" at 2.7,11.2 h1.27 r90
  text "'.Layer_Name'" at 5,-5 h3
Top Paste:
  text "'.Layer_Name'" at 5,-5 h3
Bottom Paste:
  text "'.Layer_Name'" at 5,-5 h3
Top Solder:
  text "'.Layer_Name'" at 5,-5 h3
Bottom Solder:
  text "'.Layer_Name'" at 5,-5 h3
Board Shape:
  the board outline again, w0.1
  text "'.Layer_Name'" at 5,-5 h3
Top Assembly:
  text "'.Layer_Name'" at 5,-5 h3
Bottom Assembly:
  text "'.Layer_Name'" at 5,-5 h3
Top Courtyard:
  text "'.Layer_Name'" at 5,-5 h3
Bottom Courtyard (Mech12):
  text "'.Layer_Name'" at 5,-5 h3
Top 3D Body:
  text "'.Layer_Name'" at 5,-5 h3
Bottom 3D Body:
  text "'.Layer_Name'" at 5,-5 h3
